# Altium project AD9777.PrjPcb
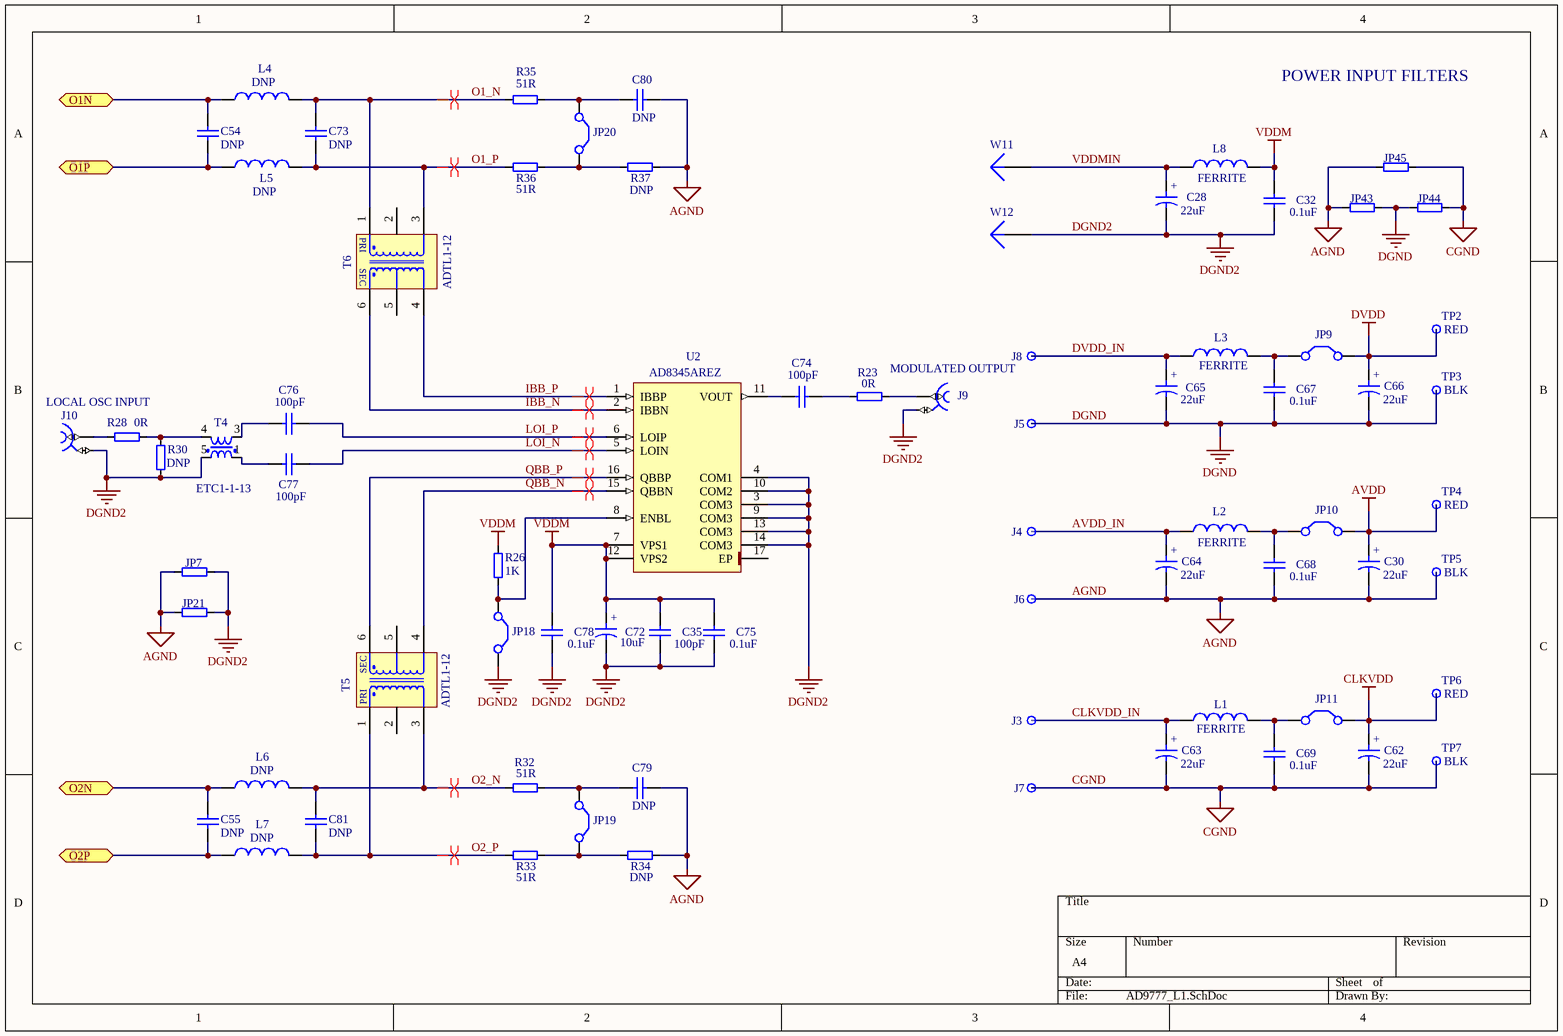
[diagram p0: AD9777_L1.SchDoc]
4 sheets, 319 parts. Net scope: flat (ports and power ports of the same name join across sheets).
Board file: AD9777_1.PcbDoc
Sheets:
  AD9777_L1.SchDoc
  AD9777_L2.SchDoc
  AD9777_L3.SchDoc
  AD9777_L4.SchDoc

## Sheet AD9777_L1.SchDoc
size A4

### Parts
(Parts that share a designator on the sheet are numbered #1, #2 ... from top to bottom, then left to right.)
C28  22uF  [CAPMP3528X210N]
C30#1  22uF  [CAPMP3528X210N]
C32  0.1uF  [CAPC2012X135N]
C35  100pF  [CAPC2012X135N]
C54  DNP  [CAPC2012X135N]
C55  DNP  [CAPC2012X135N]
C62  22uF  [CAPMP3528X210N]
C63  22uF  [CAPMP3528X210N]
C64  22uF  [CAPMP3528X210N]
C65  22uF  [CAPMP3528X210N]
C66  22uF  [CAPMP3528X210N]
C67  0.1uF  [CAPC2012X135N]
C68  0.1uF  [CAPC2012X135N]
C69  0.1uF  [CAPC2012X135N]
C72  10uF  [CAPMP3528X210N]
C73  DNP  [CAPC2012X135N]
C74  100pF  [CAPC2012X135N]
C75  0.1uF  [CAPC2012X135N]
C76  100pF  [CAPC2012X135N]
C77  100pF  [CAPC2012X135N]
C78  0.1uF  [CAPC2012X135N]
C79  DNP  [CAPC2012X135N]
C80  DNP  [CAPC2012X135N]
C81  DNP  [CAPC2012X135N]
J3  Banana  [SKS-HIRSCHMANN_930 176-101]  (value not drawn)
J4  Banana  [SKS-HIRSCHMANN_930 176-101]  (value not drawn)
J5  Banana  [SKS-HIRSCHMANN_930 176-100]  (value not drawn)
J6  Banana  [SKS-HIRSCHMANN_930 176-100]  (value not drawn)
J7  Banana  [SKS-HIRSCHMANN_930 176-100]  (value not drawn)
J8  Banana  [SKS-HIRSCHMANN_930 176-101]  (value not drawn)
J9  MODULATED OUTPUT  [AMPHENOL_132134]
J10  LOCAL OSC INPUT  [AMPHENOL_132134]
JP7  0  [RESC0603X28N]  (value not drawn)
JP9  Jumper  [PLS2]  (value not drawn)
JP10  Jumper  [PLS2]  (value not drawn)
JP11  Jumper  [PLS2]  (value not drawn)
JP18  Jumper  [PLS2]  (value not drawn)
JP19  Jumper  [PLS2]  (value not drawn)
JP20  Jumper  [PLS2]  (value not drawn)
JP21  0  [RESC0603X28N]  (value not drawn)
JP43  0  [RESC0603X28N]  (value not drawn)
JP44  0  [RESC0603X28N]  (value not drawn)
JP45  0  [RESC0603X28N]  (value not drawn)
L1  FERRITE  [6-0805_L]
L2  FERRITE  [6-0805_L]
L3  FERRITE  [6-0805_L]
L4  DNP  [6-0805_L]
L5  DNP  [6-0805_L]
L6  DNP  [6-0805_L]
L7  DNP  [6-0805_L]
L8  FERRITE  [6-0805_L]
R23  0R  [RESC2012X60N]
R26  1K  [RESC2012X60N]
R28  0R  [RESC2012X60N]
R30  DNP  [RESC2012X60N]
R32  51R  [RESC2012X60N]
R33  51R  [RESC2012X60N]
R34  DNP  [RESC2012X60N]
R35  51R  [RESC2012X60N]
R36  51R  [RESC2012X60N]
R37  DNP  [RESC2012X60N]
T4  ETC1-1-13  [XFMR_MA-COM_SM-22 (H260)]
T5  ADTL1-12  [XFMR_COILCRAFT_PWB]
T6  ADTL1-12  [XFMR_COILCRAFT_PWB]
TP2  RED  [VERO_20-2136]
TP3  BLK  [VERO_20-2136]
TP4  RED  [VERO_20-2136]
TP5  BLK  [VERO_20-2136]
TP6  RED  [VERO_20-2136]
TP7  BLK  [VERO_20-2136]
U2  AD8345AREZ  [SOP65P640X105-17N-S300]
W11  RED  [PIN1]  (value not drawn)
W12  RED  [PIN1]  (value not drawn)

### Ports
O1N, O1P, O2N, O2P

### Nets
AGND: C30#1.2 C64.2 C68.2 C79.2 C80.1 J6.1 JP7.1 JP21.1 JP43.1 JP45.1 R34.2 R37.2 TP5.1
AVDD: C30#1.1 JP10.2(C2) TP4.1
CGND: C62.2 C63.2 C69.2 J7.1 JP44.2 JP45.2 TP7.1
CLKVDD: C62.1 JP11.2(C2) TP6.1
DGND: C65.2 C66.2 C67.2 J5.1 JP43.2 JP44.1 TP3.1
DGND2: C28.2 C32.2 C35.2 C72.2 C75.2 C78.2 J9.2 J10.2 JP7.2 JP18.2(C2) JP21.2 R30.1 T4.5 U2.3(COM3) U2.4(COM1) U2.9(COM3) U2.10(COM2) U2.13(COM3) U2.14(COM3) W12.1
DVDD: C66.1 JP9.2(C2) TP2.1
VDDM: C32.1 C35.1 C72.1 C75.1 C78.1 L8.1 R26.2 U2.7(VPS1) U2.12(VPS2)
AVDD_IN: C64.1 J4.1 L2.2
CLKVDD_IN: C63.1 J3.1 L1.2
DVDD_IN: C65.1 J8.1 L3.2
IBB_N: T6.6(SDOT1) U2.2(IBBN)
IBB_P: T6.4(S) U2.1(IBBP)
LOI_N: C77.2 U2.5(LOIN)
LOI_P: C76.2 U2.6(LOIP)
O1_N: C73.2 L4.1 R35.1 T6.1(PDOT1)
O1_P: C73.1 L5.1 R36.1 T6.3(P)
O2_N: C81.2 L6.1 R32.1 T5.3(P)
O2_P: C81.1 L7.1 R33.1 T5.1(PDOT1)
QBB_N: T5.4(S) U2.15(QBBN)
QBB_P: T5.6(SDOT1) U2.16(QBBP)
VDDMIN: C28.1 L8.2 W11.1
NetC54_1: C54.1 L5.2 ; port O1P
NetC54_2: C54.2 L4.2 ; port O1N
NetC55_1: C55.1 L7.2 ; port O2P
NetC55_2: C55.2 L6.2 ; port O2N
NetC67_1: C67.1 JP9.1(C1) L3.1
NetC68_1: C68.1 JP10.1(C1) L2.1
NetC69_1: C69.1 JP11.1(C1) L1.1
NetC74_1: C74.1 U2.11(VOUT)
NetC74_2: C74.2 R23.1
NetC76_1: C76.1 T4.3
NetC77_1: C77.1 T4.1
NetC79_1: C79.1 JP19.1(C1) R32.2
NetC80_2: C80.2 JP20.1(C1) R35.2
NetJ9_1: J9.1 R23.2
NetJ10_1: J10.1 R28.1
NetJP18_1: JP18.1(C1) R26.1 U2.8(ENBL)
NetJP19_2: JP19.2(C2) R33.2 R34.1
NetJP20_2: JP20.2(C2) R36.2 R37.1
NetR28_2: R28.2 R30.2 T4.4

Not connected (* = marked no-connect by the designer): T5 2(PDOT2) 5(SDOT2); T6 2(PDOT2) 5(SDOT2); U2 17(EP)

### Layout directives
differential pair: IBB_N, IBB_P, LOI_N, LOI_P, O1_N, O1_P, O2_N, O2_P, QBB_N, QBB_P

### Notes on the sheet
- POWER INPUT FILTERS

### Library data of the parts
C28 C30#1 C62-C66 C72 = CTE3528-21_2.2UF_25V_10%: Polarised capacitor; Part Description: Solid Tantalum Chip Capacitor; Manufacturer: GENERIC; Manufacturer1 Part Number: TAJB225K025R; Voltage: 25V; Tolerance: ±10%; Table: Capacitors SMD
C32 C35 C54 C55 C67-C69 C73-C81 = CC0805_NO-VALUE: Non-polarised capacitor; Part Description: Reserved Footprint For 0805(2012) Chip Ceramic Capacitor; Manufacturer: Undefined; Mounted: No; Table: Capacitors SMD
J3 J4 J8 = SKS-HIRSCHMANN_930 176-101: Single Terminal Socket; Part Description: BIL 20 Red Socket For Banana 4mm; Manufacturer: SKS KONTATTECHNIK - HIRSCHMANN; PressFit: No
J5-J7 = SKS-HIRSCHMANN_930 176-100: Single Terminal Socket; Part Description: BIL 20 Black Socket For Banana 4mm; Manufacturer: SKS KONTATTECHNIK - HIRSCHMANN; PressFit: No
J9 J10 = AMPHENOL_132134: Part Description: 50 Ohm Through Hole SMA Straight PCB Jack; Manufacturer Part Number: 132134
JP7 JP21 JP43-JP45 = R0201_0R_JUMPER: Resistor; Part Description: 1A (0.05R Max DC Resistance) Zero Ohm Jumper; Manufacturer: GENERIC; Manufacturer1 Part Number: CRCW02010000Z0ED; PressFit: No
JP9-JP11 JP18-JP20 = Jumper: Jumper Wire
L1-L8 = Ind: Inductor; Value: 3.3u
R23 R26 R28 R30 R32-R37 = R0805_NO-VALUE: Resistor; Part Description: Reserved Footprint For a 0805 (2012) Chip Resistor; Manufacturer: Undefined; Mounted: No; Table: Resistors SMD
T4 = XFMR_MA-COM_MABA-007159-000000: MA-COM E-Serie RF 1:1 Transmission Line Ttransformer 4.5-3000MHz; Part Description: RF Transmission Line Ttransformer 4.5-3000MHz (E-Serie); Manufacturer: MA-COM TECHNOLOGY; Table: Transformers
T5 T6 = XFMR_COILCRAFT_PWB-1-BLC: SMT Transformer PWB Serie Type B Pinout; Part Description: Surface Mount Wideband RF Transformer, PWB Series
TP2-TP7 = VERO_20-2136: Test Point; Part Description: Black Bead PCB Terminal Test Pin for 1.6mm PCB Thickness (1.32mm Hole); Manufacturer: VERO TECHNOLOGIES; PressFit: No
U2 = AD8345AREZ: 140MHz to 1000MHz Quadrature Modulator; Manufacturer: ANALOG DEVICES; PressFit: No; Bonding: No
W11 W12 = Plug

## Sheet AD9777_L2.SchDoc
size A3
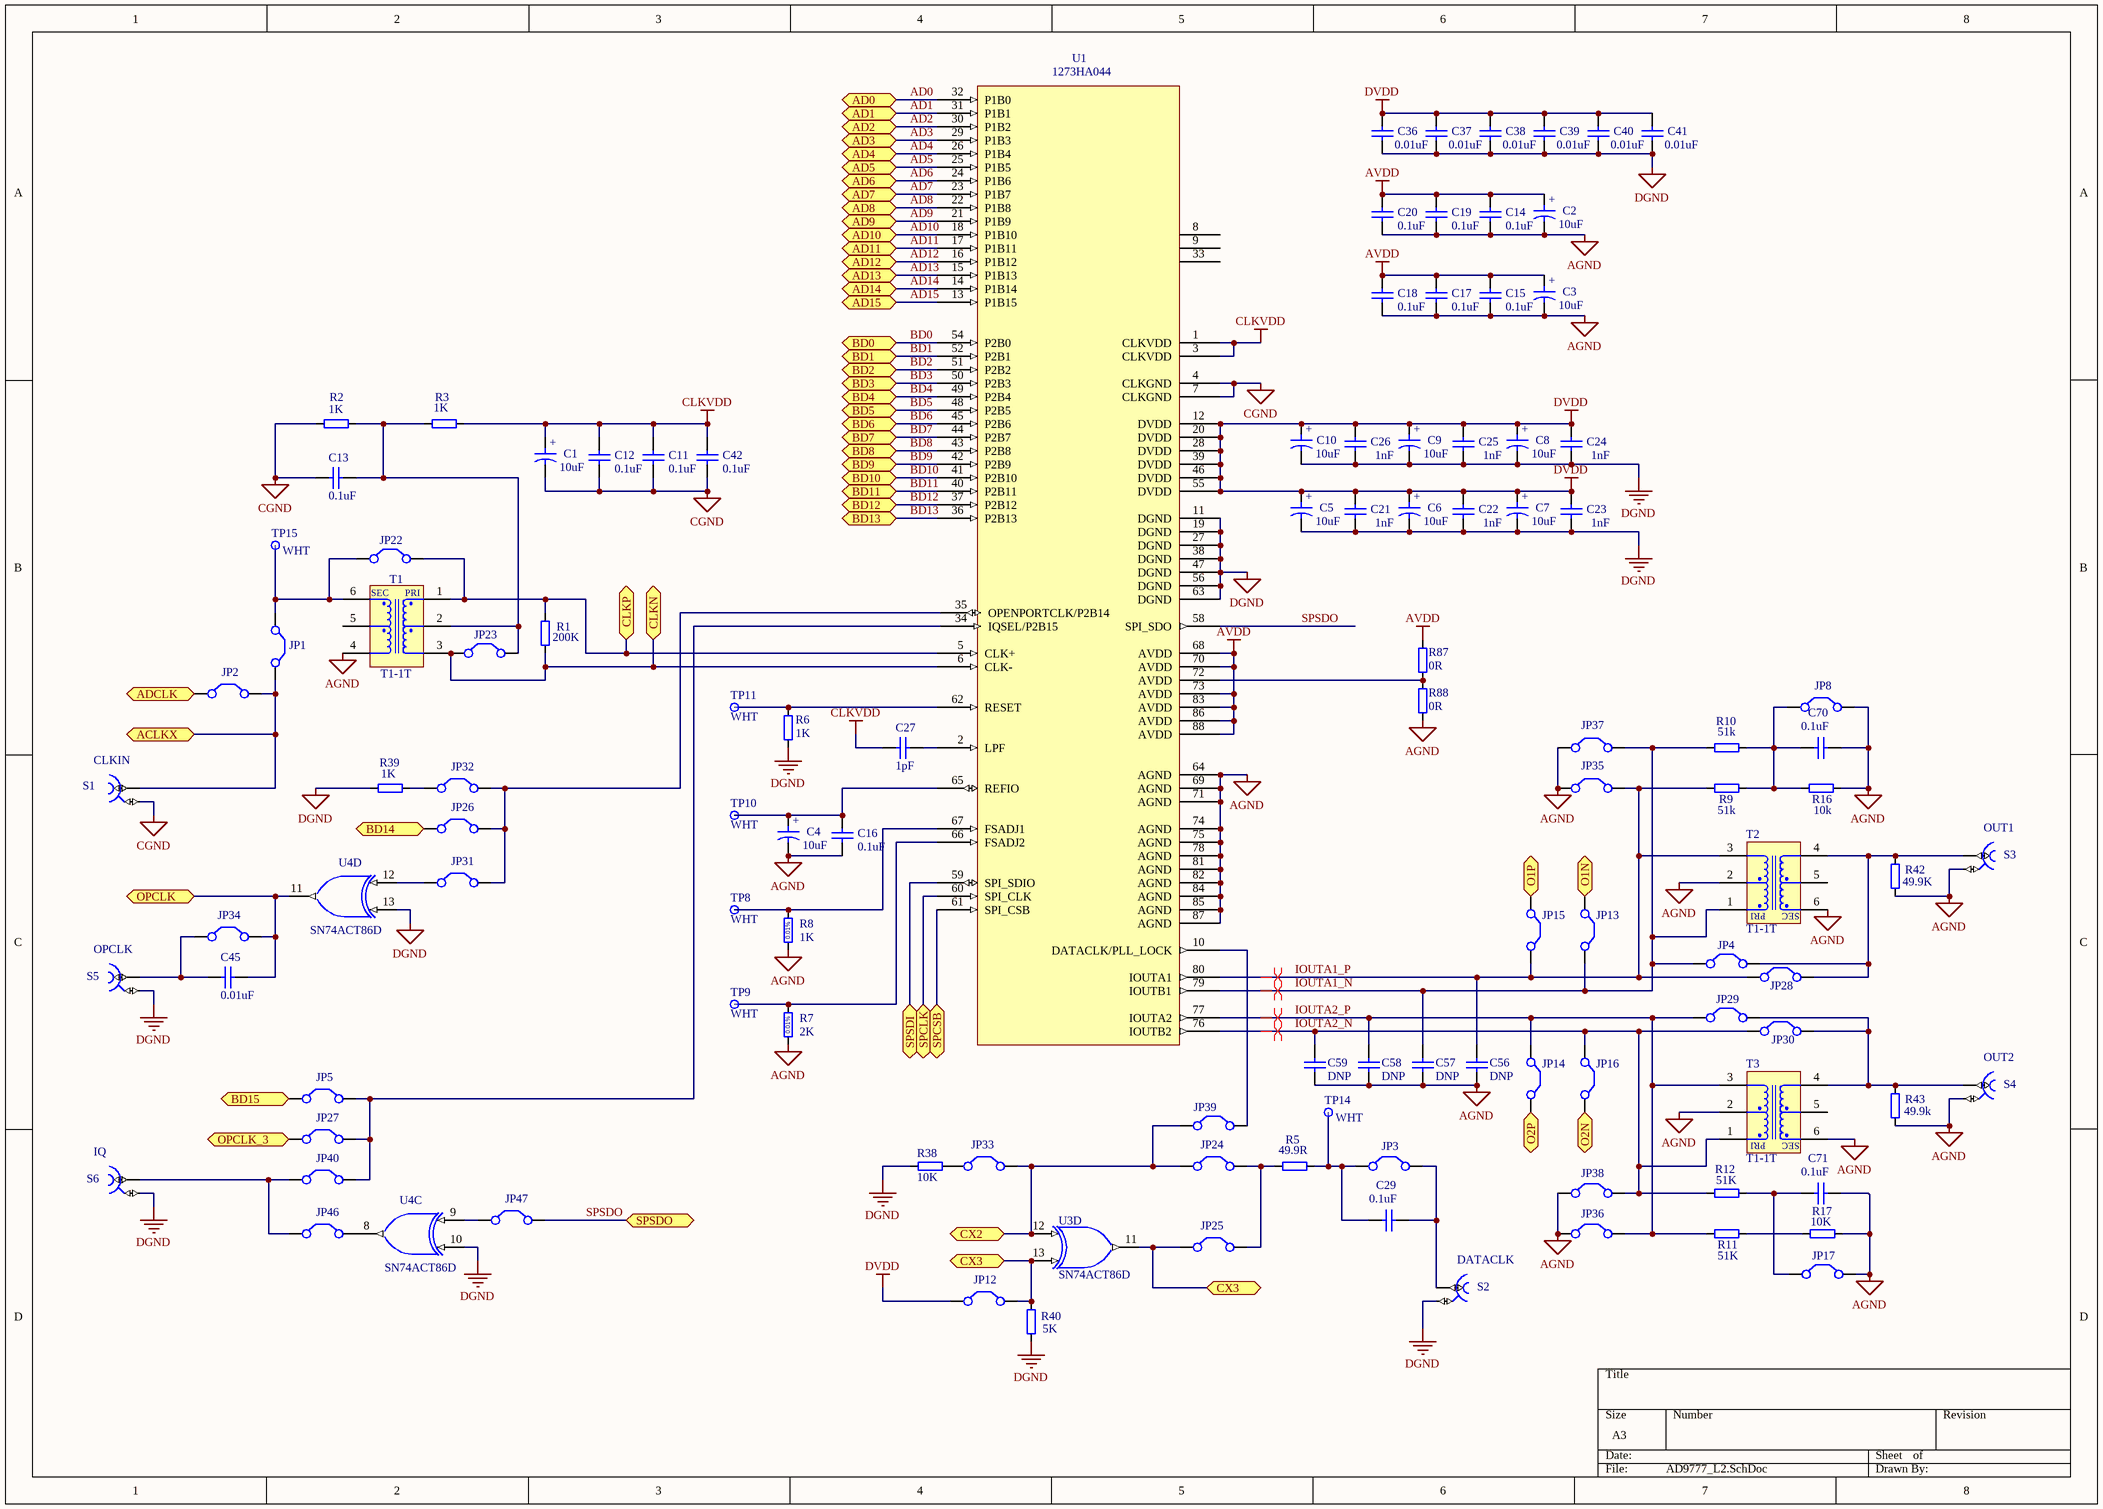
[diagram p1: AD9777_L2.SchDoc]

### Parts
C1  10uF  [CAPMP3528X210N]
C2  10uF  [CAPMP3528X210N]
C3  10uF  [CAPMP3528X210N]
C4  10uF  [CAPMP3528X210N]
C5  10uF  [CAPMP3528X210N]
C6  10uF  [CAPMP3528X210N]
C7  10uF  [CAPMP3528X210N]
C8  10uF  [CAPMP3528X210N]
C9  10uF  [CAPMP3528X210N]
C10  10uF  [CAPMP3528X210N]
C11  0.1uF  [CAPC2012X135N]
C12  0.1uF  [CAPC2012X135N]
C13  0.1uF  [CAPC2012X135N]
C14  0.1uF  [CAPC2012X135N]
C15  0.1uF  [CAPC2012X135N]
C16  0.1uF  [CAPC2012X135N]
C17  0.1uF  [CAPC2012X135N]
C18  0.1uF  [CAPC2012X135N]
C19  0.1uF  [CAPC2012X135N]
C20  0.1uF  [CAPC2012X135N]
C21  1nF  [CAPC2012X135N]
C22  1nF  [CAPC2012X135N]
C23  1nF  [CAPC2012X135N]
C24  1nF  [CAPC2012X135N]
C25  1nF  [CAPC2012X135N]
C26  1nF  [CAPC2012X135N]
C27  1pF  [CAPC2012X135N]
C29  0.1uF  [CAPC2012X135N]
C36  0.01uF  [CAPC2012X135N]
C37  0.01uF  [CAPC2012X135N]
C38  0.01uF  [CAPC2012X135N]
C39  0.01uF  [CAPC2012X135N]
C40  0.01uF  [CAPC2012X135N]
C41  0.01uF  [CAPC2012X135N]
C42  0.1uF  [CAPC2012X135N]
C45  0.01uF  [CAPC2012X135N]
C56  DNP  [CAPC2012X135N]
C57  DNP  [CAPC2012X135N]
C58  DNP  [CAPC2012X135N]
C59  DNP  [CAPC2012X135N]
C70  0.1uF  [CAPC2012X135N]
C71  0.1uF  [CAPC2012X135N]
JP1  Jumper  [PLS2]  (value not drawn)
JP2  Jumper  [PLS2]  (value not drawn)
JP3  Jumper  [PLS2]  (value not drawn)
JP4  Jumper  [PLS2]  (value not drawn)
JP5  Jumper  [PLS2]  (value not drawn)
JP8  Jumper  [PLS2]  (value not drawn)
JP12  Jumper  [PLS2]  (value not drawn)
JP13  Jumper  [PLS2]  (value not drawn)
JP14  Jumper  [PLS2]  (value not drawn)
JP15  Jumper  [PLS2]  (value not drawn)
JP16  Jumper  [PLS2]  (value not drawn)
JP17  Jumper  [PLS2]  (value not drawn)
JP22  Jumper  [PLS2]  (value not drawn)
JP23  Jumper  [PLS2]  (value not drawn)
JP24  Jumper  [PLS2]  (value not drawn)
JP25  Jumper  [PLS2]  (value not drawn)
JP26  Jumper  [PLS2]  (value not drawn)
JP27  Jumper  [PLS2]  (value not drawn)
JP28  Jumper  [PLS2]  (value not drawn)
JP29  Jumper  [PLS2]  (value not drawn)
JP30  Jumper  [PLS2]  (value not drawn)
JP31  Jumper  [PLS2]  (value not drawn)
JP32  Jumper  [PLS2]  (value not drawn)
JP33  Jumper  [PLS2]  (value not drawn)
JP34  Jumper  [PLS2]  (value not drawn)
JP35  Jumper  [PLS2]  (value not drawn)
JP36  Jumper  [PLS2]  (value not drawn)
JP37  Jumper  [PLS2]  (value not drawn)
JP38  Jumper  [PLS2]  (value not drawn)
JP39  Jumper  [PLS2]  (value not drawn)
JP40  Jumper  [PLS2]  (value not drawn)
JP46  Jumper  [PLS2]  (value not drawn)
JP47  Jumper  [PLS2]  (value not drawn)
R1  200K  [RESC2012X60N]
R2  1K  [RESC2012X60N]
R3  1K  [RESC2012X60N]
R5  49.9R  [RESC2012X60N]
R6  1K  [RESC2012X60N]
R7  2K  [RESC2013X64N]
R8  1K  [RESC2013X64N]
R9  51k  [RESC2012X60N]
R10  51k  [RESC2012X60N]
R11  51K  [RESC2012X60N]
R12  51K  [RESC2012X60N]
R16  10k  [RESC2012X60N]
R17  10K  [RESC2012X60N]
R38  10K  [RESC2012X60N]
R39  1K  [RESC2012X60N]
R40  5K  [RESC2012X60N]
R42  49.9K  [RESC2012X60N]
R43  49.9k  [RESC2012X60N]
R87  0R  [RESC2012X60N]
R88  0R  [RESC2012X60N]
S1  CLKIN  [AMPHENOL_132134]
S2  DATACLK  [AMPHENOL_132134]
S3  OUT1  [AMPHENOL_132134]
S4  OUT2  [AMPHENOL_132134]
S5  OPCLK  [AMPHENOL_132134]
S6  IQ  [AMPHENOL_132134]
T1  T1-1T  [XFMR_COILCRAFT_Q4470]
T2  T1-1T  [XFMR_COILCRAFT_Q4470]
T3  T1-1T  [XFMR_COILCRAFT_Q4470]
TP8  WHT  [VERO_20-2136]
TP9  WHT  [VERO_20-2136]
TP10  WHT  [VERO_20-2136]
TP11  WHT  [VERO_20-2136]
TP14  WHT  [VERO_20-2136]
TP15  WHT  [VERO_20-2136]
U1  1273HA044  [4235.88-1]
U3  SN74ACT86D  [SOIC127P600X175-14N]  (part D of 4)
U4  SN74ACT86D  [SOIC127P600X175-14N]  (parts C,D of 4)

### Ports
ACLKX, AD0, AD1, AD2, AD3, AD4, AD5, AD6, AD7, AD8, AD9, AD10, AD11, AD12, AD13, AD14, AD15, ADCLK, BD0, BD1, BD2, BD3, BD4, BD5, BD6, BD7, BD8, BD9, BD10, BD11, BD12, BD13, BD14, BD15, CLKN, CLKP, CX2, CX3, O1N, O1P, O2N, O2P, OPCLK, OPCLK_3, SPCLK, SPCSB, SPSDI, SPSDO

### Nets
AGND: C2.2 C3.2 C4.2 C14.2 C15.2 C16.2 C17.2 C18.2 C19.2 C20.2 C56.1 C57.1 C58.1 C59.1 C70.2 C71.2 JP8.2(C2) JP17.2(C2) JP35.1(C1) JP36.1(C1) JP37.1(C1) JP38.1(C1) R7.1 R8.1 R16.1 R17.1 R42.2 R43.2 R88.2 S3.2 S4.2 T1.4(S) T2.2(PDOT2) T2.6(SDOT1) T3.2(PDOT2) T3.6(SDOT1) U1.64(AGND) U1.69(AGND) U1.71(AGND) U1.74(AGND) U1.75(AGND) U1.78(AGND) U1.81(AGND) U1.82(AGND) U1.84(AGND) U1.85(AGND) U1.87(AGND)
AVDD: C2.1 C3.1 C14.1 C15.1 C17.1 C18.1 C19.1 C20.1 R87.1 U1.68(AVDD) U1.70(AVDD) U1.73(AVDD) U1.83(AVDD) U1.86(AVDD) U1.88(AVDD)
CGND: C1.2 C11.2 C12.2 C13.1 C42.2 R2.1 S1.2 U1.4(CLKGND) U1.7(CLKGND)
CLKVDD: C1.1 C11.1 C12.1 C27.1 C42.1 R3.2 U1.1(CLKVDD) U1.3(CLKVDD)
DGND: C5.2 C6.2 C7.2 C8.2 C9.2 C10.2 C21.2 C22.2 C23.2 C24.2 C25.2 C26.2 C36.2 C37.2 C38.2 C39.2 C40.2 C41.2 R6.1 R38.1 R39.2 R40.1 S2.2 S5.2 S6.2 U1.11(DGND) U1.19(DGND) U1.27(DGND) U1.38(DGND) U1.47(DGND) U1.56(DGND) U1.63(DGND) U4.10(B) U4.13(B)
DVDD: C5.1 C6.1 C7.1 C8.1 C9.1 C10.1 C21.1 C22.1 C23.1 C24.1 C25.1 C26.1 C36.1 C37.1 C38.1 C39.1 C40.1 C41.1 JP12.1(C1) U1.12(DVDD) U1.20(DVDD) U1.28(DVDD) U1.39(DVDD) U1.46(DVDD) U1.55(DVDD)
GND: U3.7(GND) U4.7(GND)
VCC: U3.14(VCC) U4.14(VCC)
AD0: U1.32(P1B0) ; port AD0
AD1: U1.31(P1B1) ; port AD1
AD2: U1.30(P1B2) ; port AD2
AD3: U1.29(P1B3) ; port AD3
AD4: U1.26(P1B4) ; port AD4
AD5: U1.25(P1B5) ; port AD5
AD6: U1.24(P1B6) ; port AD6
AD7: U1.23(P1B7) ; port AD7
AD8: U1.22(P1B8) ; port AD8
AD9: U1.21(P1B9) ; port AD9
AD10: U1.18(P1B10) ; port AD10
AD11: U1.17(P1B11) ; port AD11
AD12: U1.16(P1B12) ; port AD12
AD13: U1.15(P1B13) ; port AD13
AD14: U1.14(P1B14) ; port AD14
AD15: U1.13(P1B15) ; port AD15
BD0: U1.54(P2B0) ; port BD0
BD1: U1.52(P2B1) ; port BD1
BD2: U1.51(P2B2) ; port BD2
BD3: U1.50(P2B3) ; port BD3
BD4: U1.49(P2B4) ; port BD4
BD5: U1.48(P2B5) ; port BD5
BD6: U1.45(P2B6) ; port BD6
BD7: U1.44(P2B7) ; port BD7
BD8: U1.43(P2B8) ; port BD8
BD9: U1.42(P2B9) ; port BD9
BD10: U1.41(P2B10) ; port BD10
BD11: U1.40(P2B11) ; port BD11
BD12: U1.37(P2B12) ; port BD12
BD13: U1.36(P2B13) ; port BD13
IOUTA1_N: C57.2 JP4.1(C1) JP13.2(C2) JP37.2(C2) R10.2 T2.1(PDOT1) U1.79(IOUTB1)
IOUTA1_P: C56.2 JP15.2(C2) JP28.1(C1) JP35.2(C2) R9.2 T2.3(P) U1.80(IOUTA1)
IOUTA2_N: C59.2 JP16.1(C1) JP30.1(C1) JP38.2(C2) R12.2 T3.1(PDOT1) U1.76(IOUTB2)
IOUTA2_P: C58.2 JP14.1(C1) JP29.1(C1) JP36.2(C2) R11.2 T3.3(P) U1.77(IOUTA2)
SPSDO: JP47.2(C2) U1.58(SPI_SDO) ; port SPSDO
NetC4_1: C4.1 C16.1 TP10.1 U1.65(REFIO)
NetC13_2: C13.2 JP23.2(C2) R2.2 R3.1 T1.2(PDOT2)
NetC27_2: C27.2 U1.2(LPF)
NetC29_1: C29.1 JP3.1(C1) R5.2 TP14.1
NetC29_2: C29.2 JP3.2(C2) S2.1
NetC45_1: C45.1 JP34.1(C1) S5.1
NetC45_2: C45.2 JP34.2(C2) U4.11(~{O}) ; port OPCLK
NetC54_1: JP15.1(C1) ; port O1P
NetC54_2: JP13.1(C1) ; port O1N
NetC55_1: JP14.2(C2) ; port O2P
NetC55_2: JP16.2(C2) ; port O2N
NetC70_1: C70.1 JP8.1(C1) R9.1 R10.1 R16.2
NetC71_1: C71.1 JP17.1(C1) R12.1
NetJP1_1: JP1.1(C1) JP22.1(C1) T1.6(SDOT1) TP15.1
NetJP1_2: JP1.2(C2) JP2.2(C2) S1.1 ; port ACLKX
NetJP2_1: JP2.1(C1) ; port ADCLK
NetJP4_2: JP4.2(C2) JP28.2(C2) R42.1 S3.1 T2.4(S)
NetJP5_1: JP5.1(C1) ; port BD15
NetJP5_2: JP5.2(C2) JP27.2(C2) JP40.2(C2) U1.34(IQSEL/P2B15)
NetJP12_2: JP12.2(C2) JP25.1(C1) R40.2 U3.11(~{O}) U3.13(B) ; port CX3
NetJP22_2: JP22.2(C2) R1.2 T1.1(PDOT1) U1.5(CLK+) ; port CLKP
NetJP23_1: JP23.1(C1) R1.1 T1.3(P) U1.6(CLK-) ; port CLKN
NetJP24_1: JP24.1(C1) JP33.2(C2) JP39.1(C1) U3.12(A) ; port CX2
NetJP24_2: JP24.2(C2) JP25.2(C2) R5.1
NetJP26_1: JP26.1(C1) ; port BD14
NetJP26_2: JP26.2(C2) JP31.2(C2) JP32.2(C2) U1.35(OPENPORTCLK/P2B14)
NetJP27_1: JP27.1(C1) ; port OPCLK_3
NetJP29_2: JP29.2(C2) JP30.2(C2) R43.1 S4.1 T3.4(S)
NetJP31_1: JP31.1(C1) U4.12(A)
NetJP32_1: JP32.1(C1) R39.1
NetJP33_1: JP33.1(C1) R38.2
NetJP39_2: JP39.2(C2) U1.10(DATACLK/PLL_LOCK)
NetJP40_1: JP40.1(C1) JP46.1(C1) S6.1
NetJP46_2: JP46.2(C2) U4.8(~{O})
NetJP47_1: JP47.1(C1) U4.9(A)
NetR6_2: R6.2 TP11.1 U1.62(RESET)
NetR7_2: R7.2 TP9.1 U1.66(FSADJ2)
NetR8_2: R8.2 TP8.1 U1.67(FSADJ1)
NetR11_1: R11.1 R17.2
NetR87_2: R87.2 R88.1 U1.72(AVDD)
NetU1_59: U1.59(SPI_SDIO) ; port SPSDI
NetU1_60: U1.60(SPI_CLK) ; port SPCLK
NetU1_61: U1.61(SPI_CSB) ; port SPCSB

Not connected (* = marked no-connect by the designer): T1 5(SDOT2); T2 5(SDOT2); T3 5(SDOT2); U1 8 9 33

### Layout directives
differential pair: IOUTA1_N, IOUTA1_P, IOUTA2_N, IOUTA2_P

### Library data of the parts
C1-C10 = CTE3528-21_2.2UF_25V_10%: as C28 on sheet AD9777_L1
C11-C27 C29 C36-C42 C45 C56-C59 C70 C71 = CC0805_NO-VALUE: as C32 on sheet AD9777_L1
JP1-JP5 JP8 JP12-JP17 JP22-JP40 JP46 JP47 = Jumper: Jumper Wire
R1-R3 R5 R6 R9-R12 R16 R17 R38-R40 R42 R43 R87 R88 = R0805_NO-VALUE: as R23 on sheet AD9777_L1
R7 R8 = R0805_10K_0.01%_0.2W_0.2PPM_VISHAY_VSMP: Resistor - 0.01%; Part Description: Ultra High Precision Foil Wraparound Surface Mount Chip Resistor; Manufacturer: VISHAY PRECISION; Manufacturer Part Number: Y162410K0000T9R; Power: 0.2W; TC: ±0.2ppm/°C; PressFit: No
S1-S6 = AMPHENOL_132134: as J9 on sheet AD9777_L1
T1-T3 = XFMR_COILCRAFT_Q4470-CLD: Miniature SMT Transformer
TP8-TP11 TP14 TP15 = VERO_20-2136: as TP2 on sheet AD9777_L1
U3 U4 = SN74ACT86D: Quadruple 2-Input Exclusive-OR Gates; Manufacturer: TEXAS INSTRUMENTS; PressFit: No; Bonding: No

## Sheet AD9777_L3.SchDoc
size A4
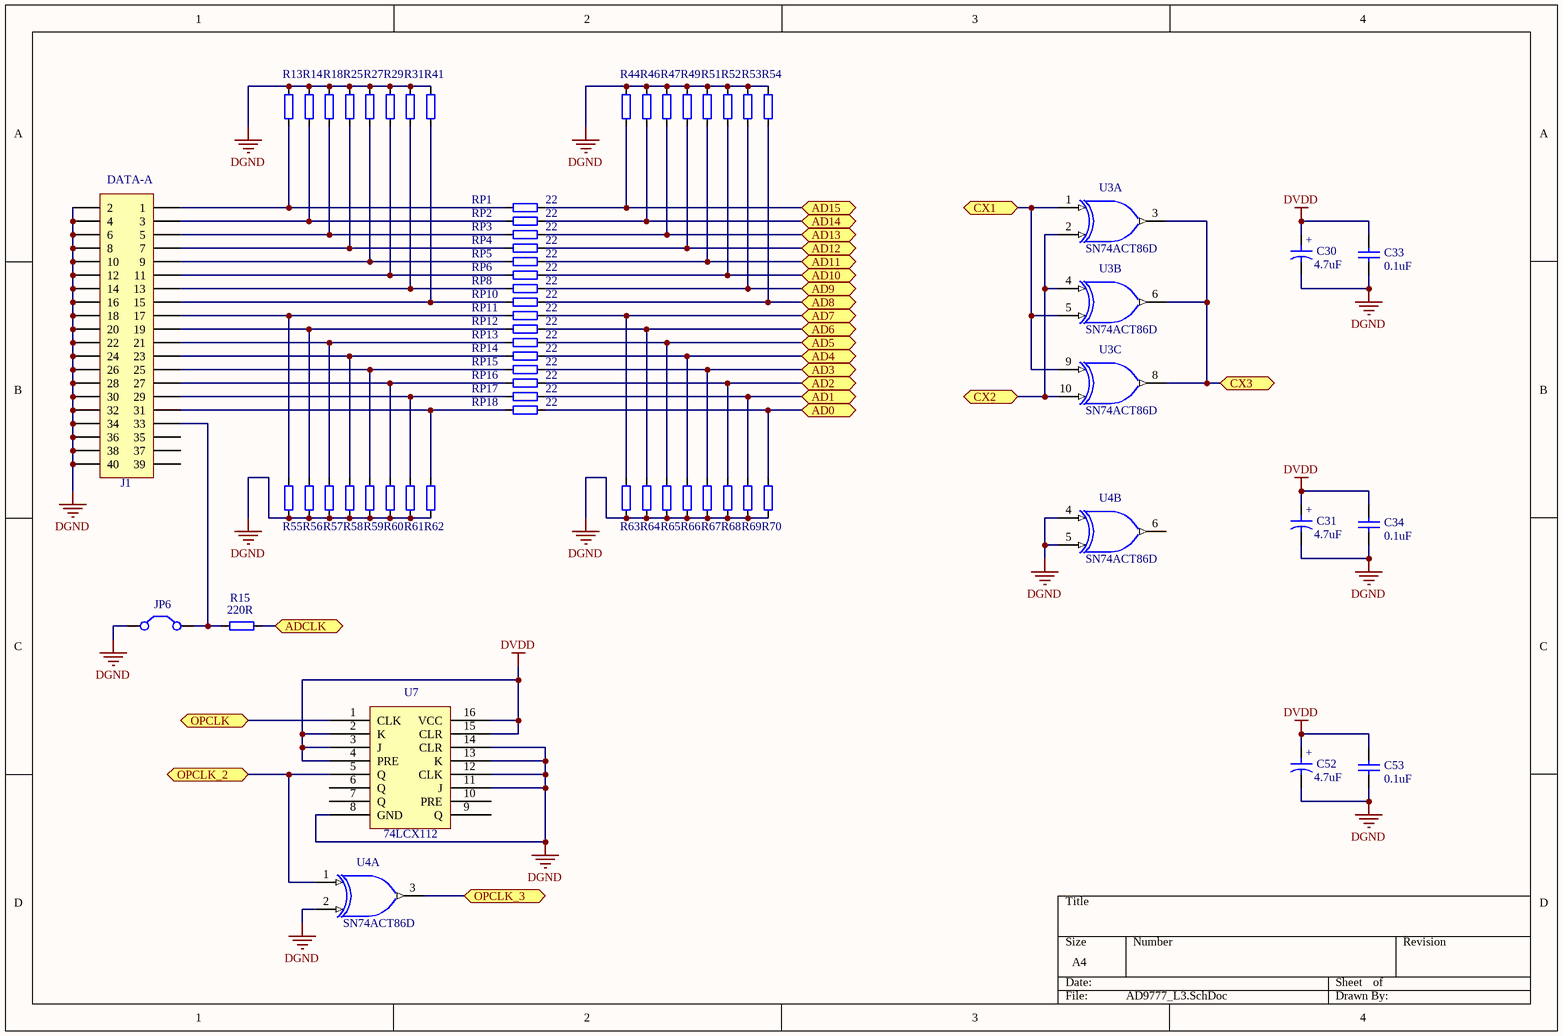
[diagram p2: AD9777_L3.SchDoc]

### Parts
(Parts that share a designator on the sheet are numbered #1, #2 ... from top to bottom, then left to right.)
C30#2  4.7uF  [CAPMP3528X210N]
C31  4.7uF  [CAPMP3528X210N]
C33  0.1uF  [CAPC2012X135N]
C34  0.1uF  [CAPC2012X135N]
C52  4.7uF  [CAPMP3528X210N]
C53  0.1uF  [CAPC2012X135N]
J1  DATA-A  [HDR2X20]
JP6  Jumper  [PLS2]  (value not drawn)
R13  50K  [RESC2012X60N]  (value not drawn)
R14  50K  [RESC2012X60N]  (value not drawn)
R15  220R  [RESC2012X60N]
R18  50K  [RESC2012X60N]  (value not drawn)
R25  50K  [RESC2012X60N]  (value not drawn)
R27  50K  [RESC2012X60N]  (value not drawn)
R29  50K  [RESC2012X60N]  (value not drawn)
R31  50K  [RESC2012X60N]  (value not drawn)
R41  50K  [RESC2012X60N]  (value not drawn)
R44  50K  [RESC2012X60N]  (value not drawn)
R46  50K  [RESC2012X60N]  (value not drawn)
R47  50K  [RESC2012X60N]  (value not drawn)
R49  50K  [RESC2012X60N]  (value not drawn)
R51  50K  [RESC2012X60N]  (value not drawn)
R52  50K  [RESC2012X60N]  (value not drawn)
R53  50K  [RESC2012X60N]  (value not drawn)
R54  50K  [RESC2012X60N]  (value not drawn)
R55  50K  [RESC2012X60N]  (value not drawn)
R56  50K  [RESC2012X60N]  (value not drawn)
R57  50K  [RESC2012X60N]  (value not drawn)
R58  50K  [RESC2012X60N]  (value not drawn)
R59  50K  [RESC2012X60N]  (value not drawn)
R60  50K  [RESC2012X60N]  (value not drawn)
R61  50K  [RESC2012X60N]  (value not drawn)
R62  50K  [RESC2012X60N]  (value not drawn)
R63  50K  [RESC2012X60N]  (value not drawn)
R64  50K  [RESC2012X60N]  (value not drawn)
R65  50K  [RESC2012X60N]  (value not drawn)
R66  50K  [RESC2012X60N]  (value not drawn)
R67  50K  [RESC2012X60N]  (value not drawn)
R68  50K  [RESC2012X60N]  (value not drawn)
R69  50K  [RESC2012X60N]  (value not drawn)
R70  50K  [RESC2012X60N]  (value not drawn)
RP1  22  [RESC2012X60N]
RP2  22  [RESC2012X60N]
RP3  22  [RESC2012X60N]
RP4  22  [RESC2012X60N]
RP5  22  [RESC2012X60N]
RP6  22  [RESC2012X60N]
RP8  22  [RESC2012X60N]
RP10  22  [RESC2012X60N]
RP11  22  [RESC2012X60N]
RP12  22  [RESC2012X60N]
RP13  22  [RESC2012X60N]
RP14  22  [RESC2012X60N]
RP15  22  [RESC2012X60N]
RP16  22  [RESC2012X60N]
RP17  22  [RESC2012X60N]
RP18  22  [RESC2012X60N]
U3  SN74ACT86D  [SOIC127P600X175-14N]  (parts A,B,C of 4)
U4  SN74ACT86D  [SOIC127P600X175-14N]  (parts A,B of 4)
U7  74LCX112  [74LCX112]

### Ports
AD0, AD1, AD2, AD3, AD4, AD5, AD6, AD7, AD8, AD9, AD10, AD11, AD12, AD13, AD14, AD15, ADCLK, CX1, CX2, CX3, OPCLK, OPCLK_2, OPCLK_3

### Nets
DGND: C30#2.2 C31.2 C33.2 C34.2 C52.2 C53.2 J1.2 J1.4 J1.6 J1.8 J1.10 J1.12 J1.14 J1.16 J1.18 J1.20 J1.22 J1.24 J1.26 J1.28 J1.30 J1.32 J1.34 J1.36 J1.38 J1.40 JP6.1(C1) R13.1 R14.1 R18.1 R25.1 R27.1 R29.1 R31.1 R41.1 R44.1 R46.1 R47.1 R49.1 R51.1 R52.1 R53.1 R54.1 R55.2 R56.2 R57.2 R58.2 R59.2 R60.2 R61.2 R62.2 R63.2 R64.2 R65.2 R66.2 R67.2 R68.2 R69.2 R70.2 U4.2(B) U4.4(A) U4.5(B) U7.8(GND) U7.11(J) U7.12(CLK) U7.13(K) U7.14(CLR)
DVDD: C30#2.1 C31.1 C33.1 C34.1 C52.1 C53.1 U7.2(K) U7.3(J) U7.4(PRE) U7.15(CLR) U7.16(VCC)
GND: U3.7(GND) U4.7(GND)
VCC: U3.14(VCC) U4.14(VCC)
AD0: R70.1 RP18.2 ; port AD0
AD1: R69.1 RP17.2 ; port AD1
AD2: R68.1 RP16.2 ; port AD2
AD3: R67.1 RP15.2 ; port AD3
AD4: R66.1 RP14.2 ; port AD4
AD5: R65.1 RP13.2 ; port AD5
AD6: R64.1 RP12.2 ; port AD6
AD7: R63.1 RP11.2 ; port AD7
AD8: R54.2 RP10.2 ; port AD8
AD9: R53.2 RP8.2 ; port AD9
AD10: R52.2 RP6.2 ; port AD10
AD11: R51.2 RP5.2 ; port AD11
AD12: R49.2 RP4.2 ; port AD12
AD13: R47.2 RP3.2 ; port AD13
AD14: R46.2 RP2.2 ; port AD14
AD15: R44.2 RP1.2 ; port AD15
NetC45_2: U7.1(CLK) ; port OPCLK
NetJ1_1: J1.1 R13.2 RP1.1
NetJ1_3: J1.3 R14.2 RP2.1
NetJ1_5: J1.5 R18.2 RP3.1
NetJ1_7: J1.7 R25.2 RP4.1
NetJ1_9: J1.9 R27.2 RP5.1
NetJ1_11: J1.11 R29.2 RP6.1
NetJ1_13: J1.13 R31.2 RP8.1
NetJ1_15: J1.15 R41.2 RP10.1
NetJ1_17: J1.17 R55.1 RP11.1
NetJ1_19: J1.19 R56.1 RP12.1
NetJ1_21: J1.21 R57.1 RP13.1
NetJ1_23: J1.23 R58.1 RP14.1
NetJ1_25: J1.25 R59.1 RP15.1
NetJ1_27: J1.27 R60.1 RP16.1
NetJ1_29: J1.29 R61.1 RP17.1
NetJ1_31: J1.31 R62.1 RP18.1
NetJ1_33: J1.33 JP6.2(C2) R15.1
NetJP2_1: R15.2 ; port ADCLK
NetJP12_2: U3.3(~{O}) U3.6(~{O}) U3.8(~{O}) ; port CX3
NetJP24_1: U3.2(B) U3.4(A) U3.10(B) ; port CX2
NetJP27_1: U4.3(~{O}) ; port OPCLK_3
NetU3_1: U3.1(A) U3.5(B) U3.9(A) ; port CX1
NetU4_1: U4.1(A) U7.5(Q) ; port OPCLK_2

Not connected (* = marked no-connect by the designer): J1 35 37 39; U4 6(~{O}); U7 6(Q) 7(Q) 9(Q) 10(PRE)

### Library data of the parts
C30#2 C31 C52 = CTE3528-21_2.2UF_25V_10%: as C28 on sheet AD9777_L1
C33 C34 C53 = CC0805_NO-VALUE: as C32 on sheet AD9777_L1
J1 = Header 20X2: Header, 20-Pin, Dual row
JP6 = Jumper: Jumper Wire
R13-R15 R18 R25 R27 R29 R31 R41 R44 R46 R47 R49 R51-R70 RP1-RP6 RP8 RP10-RP18 = R0805_NO-VALUE: as R23 on sheet AD9777_L1
U3 U4 = SN74ACT86D: as U3 on sheet AD9777_L2

## Sheet AD9777_L4.SchDoc
size A4
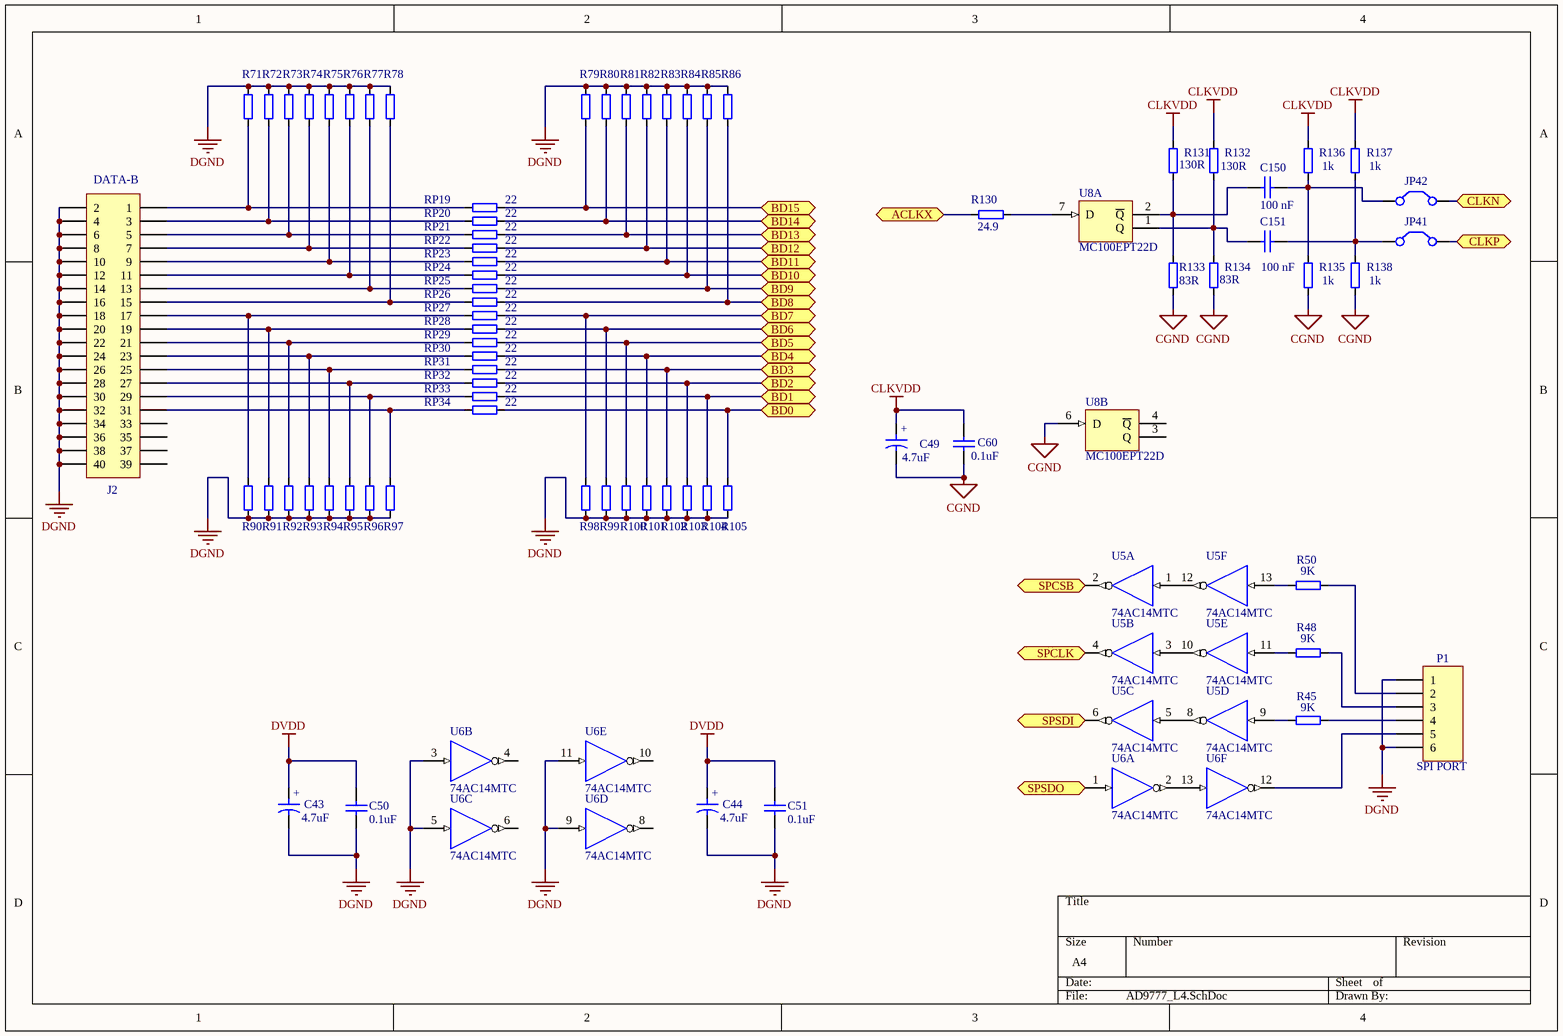
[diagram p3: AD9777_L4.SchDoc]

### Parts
C43  4.7uF  [CAPMP3528X210N]
C44  4.7uF  [CAPMP3528X210N]
C49  4.7uF  [CAPMP3528X210N]
C50  0.1uF  [CAPC2012X135N]
C51  0.1uF  [CAPC2012X135N]
C60  0.1uF  [CAPC2012X135N]
C150  100 nF  [CAPC2012X135N]
C151  100 nF  [CAPC2012X135N]
J2  DATA-B  [HDR2X20]
JP41  Jumper  [PLS2]  (value not drawn)
JP42  Jumper  [PLS2]  (value not drawn)
P1  SPI PORT  [HDR1X6]
R45  9K  [RESC2012X60N]
R48  9K  [RESC2012X60N]
R50  9K  [RESC2012X60N]
R71  50K  [RESC2012X60N]  (value not drawn)
R72  50K  [RESC2012X60N]  (value not drawn)
R73  50K  [RESC2012X60N]  (value not drawn)
R74  50K  [RESC2012X60N]  (value not drawn)
R75  50K  [RESC2012X60N]  (value not drawn)
R76  50K  [RESC2012X60N]  (value not drawn)
R77  50K  [RESC2012X60N]  (value not drawn)
R78  50K  [RESC2012X60N]  (value not drawn)
R79  50K  [RESC2012X60N]  (value not drawn)
R80  50K  [RESC2012X60N]  (value not drawn)
R81  50K  [RESC2012X60N]  (value not drawn)
R82  50K  [RESC2012X60N]  (value not drawn)
R83  50K  [RESC2012X60N]  (value not drawn)
R84  50K  [RESC2012X60N]  (value not drawn)
R85  50K  [RESC2012X60N]  (value not drawn)
R86  50K  [RESC2012X60N]  (value not drawn)
R90  50K  [RESC2012X60N]  (value not drawn)
R91  50K  [RESC2012X60N]  (value not drawn)
R92  50K  [RESC2012X60N]  (value not drawn)
R93  50K  [RESC2012X60N]  (value not drawn)
R94  50K  [RESC2012X60N]  (value not drawn)
R95  50K  [RESC2012X60N]  (value not drawn)
R96  50K  [RESC2012X60N]  (value not drawn)
R97  50K  [RESC2012X60N]  (value not drawn)
R98  50K  [RESC2012X60N]  (value not drawn)
R99  50K  [RESC2012X60N]  (value not drawn)
R100  50K  [RESC2012X60N]  (value not drawn)
R101  50K  [RESC2012X60N]  (value not drawn)
R102  50K  [RESC2012X60N]  (value not drawn)
R103  50K  [RESC2012X60N]  (value not drawn)
R104  50K  [RESC2012X60N]  (value not drawn)
R105  50K  [RESC2012X60N]  (value not drawn)
R130  24.9  [RESC2012X60N]
R131  130R  [RESC2012X60N]
R132  130R  [RESC2012X60N]
R133  83R  [RESC2012X60N]
R134  83R  [RESC2012X60N]
R135  1k  [RESC2012X60N]
R136  1k  [RESC2012X60N]
R137  1k  [RESC2012X60N]
R138  1k  [RESC2012X60N]
RP19  22  [RESC2012X60N]
RP20  22  [RESC2012X60N]
RP21  22  [RESC2012X60N]
RP22  22  [RESC2012X60N]
RP23  22  [RESC2012X60N]
RP24  22  [RESC2012X60N]
RP25  22  [RESC2012X60N]
RP26  22  [RESC2012X60N]
RP27  22  [RESC2012X60N]
RP28  22  [RESC2012X60N]
RP29  22  [RESC2012X60N]
RP30  22  [RESC2012X60N]
RP31  22  [RESC2012X60N]
RP32  22  [RESC2012X60N]
RP33  22  [RESC2012X60N]
RP34  22  [RESC2012X60N]
U5  74AC14MTC  [MTC14_N]  (parts A,B,C,D,E,F of 6)
U6  74AC14MTC  [MTC14_N]  (parts A,B,C,D,E,F of 6)
U8  MC100EPT22D  [751-06_N]  (parts A,B of 2)

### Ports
ACLKX, BD0, BD1, BD2, BD3, BD4, BD5, BD6, BD7, BD8, BD9, BD10, BD11, BD12, BD13, BD14, BD15, CLKN, CLKP, SPCLK, SPCSB, SPSDI, SPSDO

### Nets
CGND: C49.2 C60.1 R133.1 R134.1 R135.1 R138.1 U8.6(D)
CLKVDD: C49.1 C60.2 R131.2 R132.2 R136.2 R137.2
DGND: C43.2 C44.2 C50.1 C51.1 J2.2 J2.4 J2.6 J2.8 J2.10 J2.12 J2.14 J2.16 J2.18 J2.20 J2.22 J2.24 J2.26 J2.28 J2.30 J2.32 J2.34 J2.36 J2.38 J2.40 P1.1 P1.6 R71.1 R72.1 R73.1 R74.1 R75.1 R76.1 R77.1 R78.1 R79.1 R80.1 R81.1 R82.1 R83.1 R84.1 R85.1 R86.1 R90.2 R91.2 R92.2 R93.2 R94.2 R95.2 R96.2 R97.2 R98.2 R99.2 R100.2 R101.2 R102.2 R103.2 R104.2 R105.2 U6.3(I) U6.5(I) U6.9(I) U6.11(I)
DVDD: C43.1 C44.1 C50.2 C51.2
GND: U5.7(GND) U6.7(GND) U8.5(GND)
VCC: U5.14(VCC) U6.14(VCC) U8.8(VCC)
BD0: R105.1 RP34.2 ; port BD0
BD1: R104.1 RP33.2 ; port BD1
BD2: R103.1 RP32.2 ; port BD2
BD3: R102.1 RP31.2 ; port BD3
BD4: R101.1 RP30.2 ; port BD4
BD5: R100.1 RP29.2 ; port BD5
BD6: R99.1 RP28.2 ; port BD6
BD7: R98.1 RP27.2 ; port BD7
BD8: R86.2 RP26.2 ; port BD8
BD9: R85.2 RP25.2 ; port BD9
BD10: R84.2 RP24.2 ; port BD10
BD11: R83.2 RP23.2 ; port BD11
BD12: R82.2 RP22.2 ; port BD12
BD13: R81.2 RP21.2 ; port BD13
SPSDO: U6.1(I) ; port SPSDO
NetC150_1: C150.1 R131.1 R133.2 U8.2(~{Q})
NetC150_2: C150.2 JP42.1(C1) R135.2 R136.1
NetC151_1: C151.1 R132.1 R134.2 U8.1(Q)
NetC151_2: C151.2 JP41.1(C1) R137.1 R138.2
NetJ2_1: J2.1 R71.2 RP19.1
NetJ2_3: J2.3 R72.2 RP20.1
NetJ2_5: J2.5 R73.2 RP21.1
NetJ2_7: J2.7 R74.2 RP22.1
NetJ2_9: J2.9 R75.2 RP23.1
NetJ2_11: J2.11 R76.2 RP24.1
NetJ2_13: J2.13 R77.2 RP25.1
NetJ2_15: J2.15 R78.2 RP26.1
NetJ2_17: J2.17 R90.1 RP27.1
NetJ2_19: J2.19 R91.1 RP28.1
NetJ2_21: J2.21 R92.1 RP29.1
NetJ2_23: J2.23 R93.1 RP30.1
NetJ2_25: J2.25 R94.1 RP31.1
NetJ2_27: J2.27 R95.1 RP32.1
NetJ2_29: J2.29 R96.1 RP33.1
NetJ2_31: J2.31 R97.1 RP34.1
NetJP1_2: R130.1 ; port ACLKX
NetJP5_1: R79.2 RP19.2 ; port BD15
NetJP22_2: JP41.2(C2) ; port CLKP
NetJP23_1: JP42.2(C2) ; port CLKN
NetJP26_1: R80.2 RP20.2 ; port BD14
NetP1_2: P1.2 R50.1
NetP1_3: P1.3 R48.2
NetP1_4: P1.4 R45.2
NetP1_5: P1.5 U6.12(~{O})
NetR45_1: R45.1 U5.9(I)
NetR48_1: R48.1 U5.11(I)
NetR50_2: R50.2 U5.13(I)
NetR130_2: R130.2 U8.7(D)
NetU1_59: U5.6(~{O}) ; port SPSDI
NetU1_60: U5.4(~{O}) ; port SPCLK
NetU1_61: U5.2(~{O}) ; port SPCSB
NetU5_1: U5.1(I) U5.12(~{O})
NetU5_3: U5.3(I) U5.10(~{O})
NetU5_5: U5.5(I) U5.8(~{O})
NetU6_2: U6.2(~{O}) U6.13(I)

Not connected (* = marked no-connect by the designer): J2 33 35 37 39; U6 4(~{O}) 6(~{O}) 8(~{O}) 10(~{O}); U8 3(Q) 4(~{Q})

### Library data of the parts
C43 C44 C49 = CTE3528-21_2.2UF_25V_10%: as C28 on sheet AD9777_L1
C50 C51 C60 C150 C151 = CC0805_NO-VALUE: as C32 on sheet AD9777_L1
J2 = Header 20X2: Header, 20-Pin, Dual row
JP41 JP42 = Jumper: Jumper Wire
P1 = Header 6: Header, 6-Pin
R45 R48 R50 R71-R86 R90-R105 R130-R138 RP19-RP34 = R0805_NO-VALUE: as R23 on sheet AD9777_L1
U5 U6 = 74AC14MTC: Hex Schmitt-Trigger Inverter, 14-Pin TSOP; IC_Technology: AC
U8 = MC100EPT22D: Dual LVTTL/LVCMOS to Differential LVPECL Translator

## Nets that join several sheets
AGND: AD9777_L1 (13 pins), AD9777_L2 (47 pins)
AVDD: AD9777_L1 (C30#1.1 JP10.2 TP4.1), AD9777_L2 (15 pins)
CGND: AD9777_L1 (7 pins), AD9777_L2 (9 pins), AD9777_L4 (7 pins)
CLKVDD: AD9777_L1 (C62.1 JP11.2 TP6.1), AD9777_L2 (8 pins), AD9777_L4 (6 pins)
DGND: AD9777_L1 (7 pins), AD9777_L2 (34 pins), AD9777_L3 (67 pins), AD9777_L4 (62 pins)
DVDD: AD9777_L1 (C66.1 JP9.2 TP2.1), AD9777_L2 (25 pins), AD9777_L3 (11 pins), AD9777_L4 (C43.1 C44.1 C50.2 C51.2)
GND: AD9777_L2 (U3.7 U4.7), AD9777_L3 (U3.7 U4.7), AD9777_L4 (U5.7 U6.7 U8.5)
VCC: AD9777_L2 (U3.14 U4.14), AD9777_L3 (U3.14 U4.14), AD9777_L4 (U5.14 U6.14 U8.8)
AD0: AD9777_L2 (U1.32), AD9777_L3 (R70.1 RP18.2)
AD1: AD9777_L2 (U1.31), AD9777_L3 (R69.1 RP17.2)
AD2: AD9777_L2 (U1.30), AD9777_L3 (R68.1 RP16.2)
AD3: AD9777_L2 (U1.29), AD9777_L3 (R67.1 RP15.2)
AD4: AD9777_L2 (U1.26), AD9777_L3 (R66.1 RP14.2)
AD5: AD9777_L2 (U1.25), AD9777_L3 (R65.1 RP13.2)
AD6: AD9777_L2 (U1.24), AD9777_L3 (R64.1 RP12.2)
AD7: AD9777_L2 (U1.23), AD9777_L3 (R63.1 RP11.2)
AD8: AD9777_L2 (U1.22), AD9777_L3 (R54.2 RP10.2)
AD9: AD9777_L2 (U1.21), AD9777_L3 (R53.2 RP8.2)
AD10: AD9777_L2 (U1.18), AD9777_L3 (R52.2 RP6.2)
AD11: AD9777_L2 (U1.17), AD9777_L3 (R51.2 RP5.2)
AD12: AD9777_L2 (U1.16), AD9777_L3 (R49.2 RP4.2)
AD13: AD9777_L2 (U1.15), AD9777_L3 (R47.2 RP3.2)
AD14: AD9777_L2 (U1.14), AD9777_L3 (R46.2 RP2.2)
AD15: AD9777_L2 (U1.13), AD9777_L3 (R44.2 RP1.2)
BD0: AD9777_L2 (U1.54), AD9777_L4 (R105.1 RP34.2)
BD1: AD9777_L2 (U1.52), AD9777_L4 (R104.1 RP33.2)
BD2: AD9777_L2 (U1.51), AD9777_L4 (R103.1 RP32.2)
BD3: AD9777_L2 (U1.50), AD9777_L4 (R102.1 RP31.2)
BD4: AD9777_L2 (U1.49), AD9777_L4 (R101.1 RP30.2)
BD5: AD9777_L2 (U1.48), AD9777_L4 (R100.1 RP29.2)
BD6: AD9777_L2 (U1.45), AD9777_L4 (R99.1 RP28.2)
BD7: AD9777_L2 (U1.44), AD9777_L4 (R98.1 RP27.2)
BD8: AD9777_L2 (U1.43), AD9777_L4 (R86.2 RP26.2)
BD9: AD9777_L2 (U1.42), AD9777_L4 (R85.2 RP25.2)
BD10: AD9777_L2 (U1.41), AD9777_L4 (R84.2 RP24.2)
BD11: AD9777_L2 (U1.40), AD9777_L4 (R83.2 RP23.2)
BD12: AD9777_L2 (U1.37), AD9777_L4 (R82.2 RP22.2)
BD13: AD9777_L2 (U1.36), AD9777_L4 (R81.2 RP21.2)
NetC45_2: AD9777_L2 (C45.2 JP34.2 U4.11), AD9777_L3 (U7.1)
NetC54_1: AD9777_L1 (C54.1 L5.2), AD9777_L2 (JP15.1)
NetC54_2: AD9777_L1 (C54.2 L4.2), AD9777_L2 (JP13.1)
NetC55_1: AD9777_L1 (C55.1 L7.2), AD9777_L2 (JP14.2)
NetC55_2: AD9777_L1 (C55.2 L6.2), AD9777_L2 (JP16.2)
NetJP1_2: AD9777_L2 (JP1.2 JP2.2 S1.1), AD9777_L4 (R130.1)
NetJP2_1: AD9777_L2 (JP2.1), AD9777_L3 (R15.2)
NetJP5_1: AD9777_L2 (JP5.1), AD9777_L4 (R79.2 RP19.2)
NetJP12_2: AD9777_L2 (5 pins), AD9777_L3 (U3.3 U3.6 U3.8)
NetJP22_2: AD9777_L2 (JP22.2 R1.2 T1.1 U1.5), AD9777_L4 (JP41.2)
NetJP23_1: AD9777_L2 (JP23.1 R1.1 T1.3 U1.6), AD9777_L4 (JP42.2)
NetJP24_1: AD9777_L2 (JP24.1 JP33.2 JP39.1 U3.12), AD9777_L3 (U3.2 U3.4 U3.10)
NetJP26_1: AD9777_L2 (JP26.1), AD9777_L4 (R80.2 RP20.2)
NetJP27_1: AD9777_L2 (JP27.1), AD9777_L3 (U4.3)
NetU1_59: AD9777_L2 (U1.59), AD9777_L4 (U5.6)
NetU1_60: AD9777_L2 (U1.60), AD9777_L4 (U5.4)
NetU1_61: AD9777_L2 (U1.61), AD9777_L4 (U5.2)
SPSDO: AD9777_L2 (JP47.2 U1.58), AD9777_L4 (U6.1)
